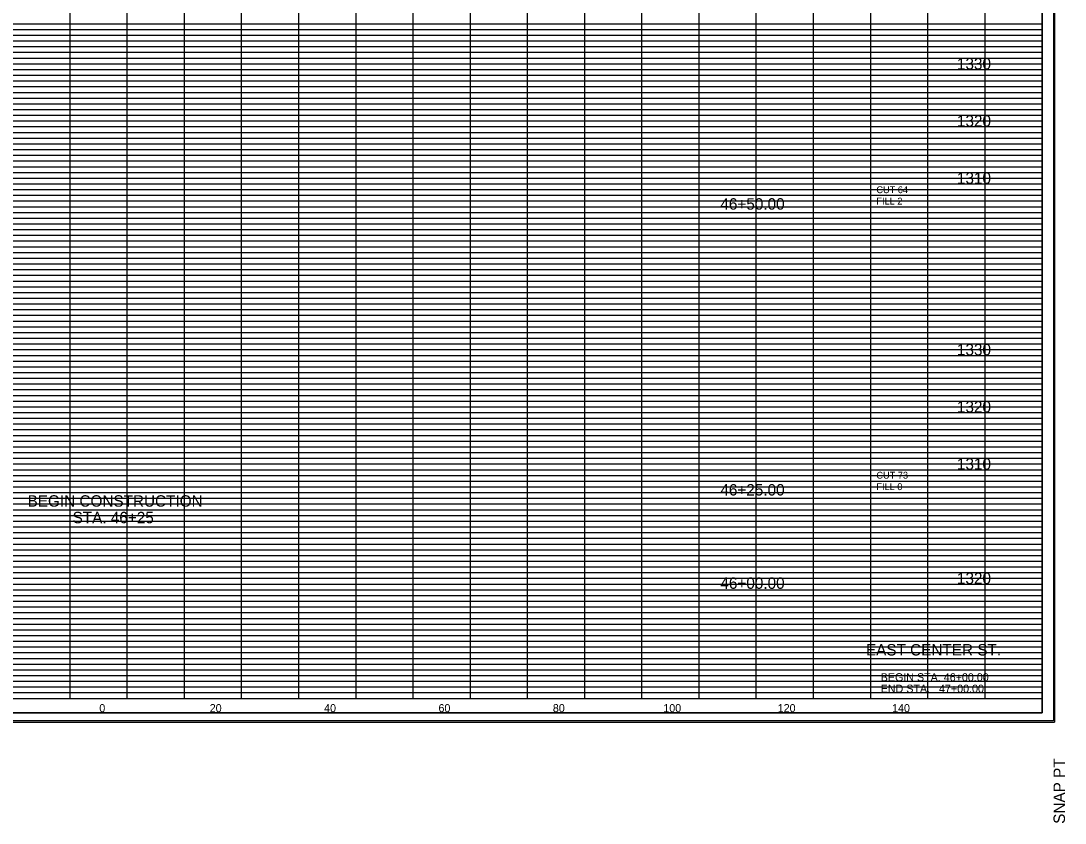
# Model space of a CAD drawing. Extents: x 980 to 1324, y 978 to 1767.
# Drawn here: x 1141.4 to 1324, y 978.2 to 1118.5 of the extents above; entities that cross this region are included whole.
import ezdxf

# ---------------------------------------------------------------- set-up
doc = ezdxf.new("R2010")
doc.units = 0
for name, color, linetype in [('DESIGN - SHEET - Corner Text', 7, 'Continuous'), ('DESIGN - SHEET - Light Grid', 7, 'Continuous'), ('DESIGN - SHEET - Linework', 7, 'Continuous'), ('DESIGN - SHEET - Plot Shape', 7, 'Continuous'), ('DESIGN - TYPICAL - Text', 7, 'Continuous')]:
    doc.layers.add(name, color=color, linetype=linetype)

# ---------------------------------------------------------------- blocks, each defined once
blk = doc.blocks.new('XSTSHT')
at = {"layer": 'DESIGN - SHEET - Light Grid'}
for p, q in [((8, 11.8), (16, 11.8)), ((8, 11.7), (16, 11.7)), ((16, 11.8), (24, 11.8)), ((16, 11.7), (24, 11.7)), ((24, 11.8), (32, 11.8)), ((24, 11.7), (32, 11.7)), ((8, 11.6), (16, 11.6)), ((16, 11.6), (24, 11.6)), ((24, 11.6), (32, 11.6)), ((8, 11.5), (16, 11.5)), ((8, 11.4), (16, 11.4)), ((16, 11.5), (24, 11.5)), ((16, 11.4), (24, 11.4)), ((24, 11.5), (32, 11.5)), ((24, 11.4), (32, 11.4)), ((8, 11.3), (16, 11.3)), ((8, 11.2), (16, 11.2)), ((16, 11.3), (24, 11.3)), ((16, 11.2), (24, 11.2)), ((24, 11.3), (32, 11.3)), ((24, 11.2), (32, 11.2)), ((8, 11.1), (16, 11.1)), ((16, 11.1), (24, 11.1)), ((24, 11.1), (32, 11.1)), ((8, 10.9), (16, 10.9)), ((8, 10.8), (16, 10.8)), ((16, 10.9), (24, 10.9)), ((16, 10.8), (24, 10.8)), ((24, 10.9), (32, 10.9)), ((24, 10.8), (32, 10.8)), ((8, 10.7), (16, 10.7)), ((8, 10.6), (16, 10.6)), ((16, 10.7), (24, 10.7)), ((16, 10.6), (24, 10.6)), ((24, 10.7), (32, 10.7)), ((24, 10.6), (32, 10.6)), ((8, 10.5), (16, 10.5)), ((16, 10.5), (24, 10.5)), ((24, 10.5), (32, 10.5)), ((8, 10.4), (16, 10.4)), ((8, 10.3), (16, 10.3)), ((16, 10.4), (24, 10.4)), ((16, 10.3), (24, 10.3)), ((24, 10.4), (32, 10.4)), ((24, 10.3), (32, 10.3)), ((8, 10.2), (16, 10.2)), ((8, 10.1), (16, 10.1)), ((16, 10.2), (24, 10.2)), ((16, 10.1), (24, 10.1)), ((24, 10.2), (32, 10.2)), ((24, 10.1), (32, 10.1)), ((8, 9.9), (16, 9.9)), ((16, 9.9), (24, 9.9)), ((24, 9.9), (32, 9.9)), ((8, 9.8), (16, 9.8)), ((8, 9.7), (16, 9.7)), ((16, 9.8), (24, 9.8)), ((16, 9.7), (24, 9.7)), ((24, 9.8), (32, 9.8)), ((24, 9.7), (32, 9.7)), ((8, 9.6), (16, 9.6)), ((8, 9.5), (16, 9.5)), ((16, 9.6), (24, 9.6)), ((16, 9.5), (24, 9.5)), ((24, 9.6), (32, 9.6)), ((24, 9.5), (32, 9.5)), ((8, 9.4), (16, 9.4)), ((16, 9.4), (24, 9.4)), ((24, 9.4), (32, 9.4)), ((8, 9.3), (16, 9.3)), ((8, 9.2), (16, 9.2)), ((16, 9.3), (24, 9.3)), ((16, 9.2), (24, 9.2)), ((24, 9.3), (32, 9.3)), ((24, 9.2), (32, 9.2)), ((8, 9.1), (16, 9.1)), ((16, 9.1), (24, 9.1)), ((24, 9.1), (32, 9.1)), ((8, 8.9), (16, 8.9)), ((8, 8.8), (16, 8.8)), ((16, 8.9), (24, 8.9)), ((16, 8.8), (24, 8.8)), ((24, 8.9), (32, 8.9)), ((24, 8.8), (32, 8.8)), ((8, 8.7), (16, 8.7)), ((8, 8.6), (16, 8.6)), ((16, 8.7), (24, 8.7)), ((16, 8.6), (24, 8.6)), ((24, 8.7), (32, 8.7)), ((24, 8.6), (32, 8.6)), ((8, 8.5), (16, 8.5)), ((8, 8.4), (16, 8.4)), ((16, 8.5), (24, 8.5)), ((16, 8.4), (24, 8.4)), ((24, 8.5), (32, 8.5)), ((24, 8.4), (32, 8.4)), ((8, 8.3), (16, 8.3)), ((16, 8.3), (24, 8.3)), ((24, 8.3), (32, 8.3)), ((8, 8.2), (16, 8.2)), ((8, 8.1), (16, 8.1)), ((16, 8.2), (24, 8.2)), ((16, 8.1), (24, 8.1)), ((24, 8.2), (32, 8.2)), ((24, 8.1), (32, 8.1)), ((8, 7.9), (16, 7.9)), ((16, 7.9), (24, 7.9)), ((24, 7.9), (32, 7.9)), ((8, 7.8), (16, 7.8)), ((8, 7.7), (16, 7.7)), ((16, 7.8), (24, 7.8)), ((16, 7.7), (24, 7.7)), ((24, 7.8), (32, 7.8)), ((24, 7.7), (32, 7.7)), ((8, 7.6), (16, 7.6)), ((8, 7.5), (16, 7.5)), ((16, 7.6), (24, 7.6)), ((16, 7.5), (24, 7.5)), ((24, 7.6), (32, 7.6)), ((24, 7.5), (32, 7.5)), ((8, 7.4), (16, 7.4)), ((16, 7.4), (24, 7.4)), ((24, 7.4), (32, 7.4)), ((8, 7.3), (16, 7.3)), ((8, 7.2), (16, 7.2)), ((16, 7.3), (24, 7.3)), ((16, 7.2), (24, 7.2)), ((24, 7.3), (32, 7.3)), ((24, 7.2), (32, 7.2)), ((8, 7.1), (16, 7.1)), ((16, 7.1), (24, 7.1)), ((24, 7.1), (32, 7.1)), ((8, 6.9), (16, 6.9)), ((8, 6.8), (16, 6.8)), ((16, 6.9), (24, 6.9)), ((16, 6.8), (24, 6.8)), ((24, 6.9), (32, 6.9)), ((24, 6.8), (32, 6.8)), ((8, 6.7), (16, 6.7)), ((8, 6.6), (16, 6.6)), ((16, 6.7), (24, 6.7)), ((16, 6.6), (24, 6.6)), ((24, 6.7), (32, 6.7)), ((24, 6.6), (32, 6.6)), ((8, 6.5), (16, 6.5)), ((8, 6.4), (16, 6.4)), ((16, 6.5), (24, 6.5)), ((16, 6.4), (24, 6.4)), ((24, 6.5), (32, 6.5)), ((24, 6.4), (32, 6.4)), ((8, 6.3), (16, 6.3)), ((16, 6.3), (24, 6.3)), ((24, 6.3), (32, 6.3)), ((8, 6.2), (16, 6.2)), ((8, 6.1), (16, 6.1)), ((16, 6.2), (24, 6.2)), ((16, 6.1), (24, 6.1)), ((24, 6.2), (32, 6.2)), ((24, 6.1), (32, 6.1)), ((8, 5.9), (16, 5.9)), ((16, 5.9), (24, 5.9)), ((24, 5.9), (32, 5.9)), ((8, 5.8), (16, 5.8)), ((8, 5.7), (16, 5.7)), ((16, 5.8), (24, 5.8)), ((16, 5.7), (24, 5.7)), ((24, 5.8), (32, 5.8)), ((24, 5.7), (32, 5.7)), ((8, 5.6), (16, 5.6)), ((8, 5.5), (16, 5.5)), ((16, 5.6), (24, 5.6)), ((16, 5.5), (24, 5.5)), ((24, 5.6), (32, 5.6)), ((24, 5.5), (32, 5.5)), ((8, 5.4), (16, 5.4)), ((8, 5.3), (16, 5.3)), ((16, 5.4), (24, 5.4)), ((16, 5.3), (24, 5.3)), ((24, 5.4), (32, 5.4)), ((24, 5.3), (32, 5.3)), ((8, 5.2), (16, 5.2)), ((16, 5.2), (24, 5.2)), ((24, 5.2), (32, 5.2)), ((8, 5.1), (16, 5.1)), ((16, 5.1), (24, 5.1)), ((24, 5.1), (32, 5.1)), ((8, 4.9), (16, 4.9)), ((8, 4.8), (16, 4.8)), ((16, 4.9), (24, 4.9)), ((16, 4.8), (24, 4.8)), ((24, 4.9), (32, 4.9)), ((24, 4.8), (32, 4.8)), ((8, 4.7), (16, 4.7)), ((8, 4.6), (16, 4.6)), ((16, 4.7), (24, 4.7)), ((16, 4.6), (24, 4.6)), ((24, 4.7), (32, 4.7)), ((24, 4.6), (32, 4.6)), ((8, 4.5), (16, 4.5)), ((8, 4.4), (16, 4.4)), ((16, 4.5), (24, 4.5)), ((16, 4.4), (24, 4.4)), ((24, 4.5), (32, 4.5)), ((24, 4.4), (32, 4.4)), ((8, 4.3), (16, 4.3)), ((8, 4.2), (16, 4.2)), ((16, 4.3), (24, 4.3)), ((16, 4.2), (24, 4.2)), ((24, 4.3), (32, 4.3)), ((24, 4.2), (32, 4.2)), ((8, 4.1), (16, 4.1)), ((16, 4.1), (24, 4.1)), ((24, 4.1), (32, 4.1)), ((8, 3.9), (16, 3.9)), ((16, 3.9), (24, 3.9)), ((24, 3.9), (32, 3.9)), ((8, 3.8), (16, 3.8)), ((8, 3.7), (16, 3.7)), ((16, 3.8), (24, 3.8)), ((16, 3.7), (24, 3.7)), ((24, 3.8), (32, 3.8)), ((24, 3.7), (32, 3.7)), ((8, 3.6), (16, 3.6)), ((8, 3.5), (16, 3.5)), ((16, 3.6), (24, 3.6)), ((16, 3.5), (24, 3.5)), ((24, 3.6), (32, 3.6)), ((24, 3.5), (32, 3.5)), ((8, 3.4), (16, 3.4)), ((8, 3.3), (16, 3.3)), ((16, 3.4), (24, 3.4)), ((16, 3.3), (24, 3.3)), ((24, 3.4), (32, 3.4)), ((24, 3.3), (32, 3.3)), ((8, 3.2), (16, 3.2)), ((16, 3.2), (24, 3.2)), ((24, 3.2), (32, 3.2)), ((8, 3.1), (16, 3.1)), ((16, 3.1), (24, 3.1)), ((24, 3.1), (32, 3.1)), ((8, 2.9), (16, 2.9)), ((8, 2.8), (16, 2.8)), ((16, 2.9), (24, 2.9)), ((16, 2.8), (24, 2.8)), ((24, 2.9), (32, 2.9)), ((24, 2.8), (32, 2.8)), ((8, 2.7), (16, 2.7)), ((8, 2.6), (16, 2.6)), ((16, 2.7), (24, 2.7)), ((16, 2.6), (24, 2.6)), ((24, 2.7), (32, 2.7)), ((24, 2.6), (32, 2.6)), ((8, 2.5), (16, 2.5)), ((8, 2.4), (16, 2.4)), ((16, 2.5), (24, 2.5)), ((16, 2.4), (24, 2.4)), ((24, 2.5), (32, 2.5)), ((24, 2.4), (32, 2.4)), ((8, 2.3), (16, 2.3)), ((8, 2.2), (16, 2.2)), ((16, 2.3), (24, 2.3)), ((16, 2.2), (24, 2.2)), ((24, 2.3), (32, 2.3)), ((24, 2.2), (32, 2.2)), ((8, 2.1), (16, 2.1)), ((16, 2.1), (24, 2.1)), ((24, 2.1), (32, 2.1)), ((8, 1.9), (16, 1.9)), ((16, 1.9), (24, 1.9)), ((24, 1.9), (32, 1.9)), ((8, 1.8), (16, 1.8)), ((8, 1.7), (16, 1.7)), ((16, 1.8), (24, 1.8)), ((16, 1.7), (24, 1.7)), ((24, 1.8), (32, 1.8)), ((24, 1.7), (32, 1.7)), ((8, 1.6), (16, 1.6)), ((8, 1.5), (16, 1.5)), ((16, 1.6), (24, 1.6)), ((16, 1.5), (24, 1.5)), ((24, 1.6), (32, 1.6)), ((24, 1.5), (32, 1.5)), ((8, 1.4), (16, 1.4)), ((8, 1.3), (16, 1.3)), ((16, 1.4), (24, 1.4)), ((16, 1.3), (24, 1.3)), ((24, 1.4), (32, 1.4)), ((24, 1.3), (32, 1.3)), ((8, 1.2), (16, 1.2)), ((8, 1.1), (16, 1.1)), ((16, 1.2), (24, 1.2)), ((16, 1.1), (24, 1.1)), ((24, 1.2), (32, 1.2)), ((24, 1.1), (32, 1.1)), ((8, 0.9), (16, 0.9)), ((8, 0.8), (16, 0.8)), ((16, 0.9), (24, 0.9)), ((16, 0.8), (24, 0.8)), ((24, 0.9), (32, 0.9)), ((24, 0.8), (32, 0.8)), ((8, 0.7), (16, 0.7)), ((8, 0.6), (16, 0.6)), ((16, 0.7), (24, 0.7)), ((16, 0.6), (24, 0.6)), ((24, 0.7), (32, 0.7)), ((24, 0.6), (32, 0.6)), ((8, 0.5), (16, 0.5)), ((8, 0.4), (16, 0.4)), ((16, 0.5), (24, 0.5)), ((16, 0.4), (24, 0.4)), ((24, 0.5), (32, 0.5)), ((24, 0.4), (32, 0.4)), ((8, 0.3), (16, 0.3)), ((8, 0.2), (16, 0.2)), ((16, 0.3), (24, 0.3)), ((16, 0.2), (24, 0.2)), ((24, 0.3), (32, 0.3)), ((24, 0.2), (32, 0.2)), ((8, 0.1), (16, 0.1)), ((16, 0.1), (24, 0.1)), ((24, 0.1), (32, 0.1))]:
    blk.add_line(p, q, dxfattribs=at)
at = {"layer": 'DESIGN - SHEET - Linework'}
for p, q in [((32.217, 21.414), (32.217, -0.414)), ((15, 0), (15, 21)), ((16, 0), (16, 21)), ((17, 0), (17, 21)), ((18, 0), (18, 21)), ((19, 0), (19, 21)), ((20, 0), (20, 21)), ((21, 0), (21, 21)), ((22, 0), (22, 21)), ((23, 0), (23, 21)), ((24, 0), (24, 21)), ((25, 0), (25, 21)), ((26, 0), (26, 21)), ((27, 0), (27, 21)), ((28, 0), (28, 20)), ((29, 0), (29, 20)), ((30, 0), (30, 20)), ((31, 0), (31, 20)), ((0, 11), (32, 11)), ((0, 10), (32, 10)), ((0, 9), (32, 9)), ((0, 8), (32, 8)), ((0, 7), (32, 7)), ((0, 6), (32, 6)), ((0, 5), (32, 5)), ((0, 4), (32, 4)), ((0, 3), (32, 3)), ((0, 2), (32, 2)), ((0, 1), (32, 1)), ((-1.823, -0.414), (32.217, -0.414))]:
    blk.add_line(p, q, dxfattribs=at)
blk.add_lwpolyline([(0, 21), (0, 0), (32, 0), (32, 21), (0, 21)], dxfattribs=at)
at = {"layer": 'DESIGN - SHEET - Plot Shape'}
for points in [[(-1.803, 21.394), (32.197, 21.394), (32.197, -0.394), (-1.803, -0.394)], [(-0.85, 21), (32, 21), (32, -0.25), (-0.85, -0.25)]]:
    blk.add_lwpolyline(points, close=True, dxfattribs=at)
at = {"layer": 'DESIGN - SHEET - Corner Text'}
blk.add_text('SNAP PT  ', height=0.2, rotation=90, dxfattribs=at).set_placement((32.397, -2.194))

msp = doc.modelspace()

# ---------------------------------------------------------------- linework, layer by layer
at = {"layer": 'DESIGN - SHEET - Plot Shape'}
msp.add_lwpolyline([(991.5, 997.5), (1320, 997.5), (1320, 1210), (991.5, 1210)], close=True, dxfattribs=at)

# ---------------------------------------------------------------- block references
at = {"layer": 'DESIGN - SHEET - Plot Shape', "xscale": 10, "yscale": 10}
msp.add_blockref('XSTSHT', (1000, 1000), dxfattribs=at)

# ---------------------------------------------------------------- texts
at = {"layer": 'DESIGN - SHEET - Corner Text'}
for s, height, p in [('EAST CENTER ST.', 2, (1289.17, 1007.5)), ('BEGIN STA. 46+00.00', 1.4, (1291.75, 1003)), ('END STA.   47+00.00', 1.4, (1291.75, 1001))]:
    msp.add_text(s, height=height, dxfattribs=at).set_placement(p)
at = {"layer": 'DESIGN - TYPICAL - Text'}
for s, height, p in [('     1330     ', 2, (1301.37, 1110)), ('     1320     ', 2, (1301.37, 1100)), ('     1310     ', 2, (1301.37, 1090)), ('CUT 64', 1.2, (1291, 1088.37)), ('     46+50.00     ', 2, (1260, 1085.48)), ('FILL 2', 1.2, (1291, 1086.37)), ('     1330     ', 2, (1301.37, 1060)), ('     1320     ', 2, (1301.37, 1050)), ('     1310     ', 2, (1301.37, 1040)), ('CUT 73', 1.2, (1291, 1038.43)), ('     46+25.00     ', 2, (1260, 1035.48)), ('FILL 0', 1.2, (1291, 1036.43)), ('BEGIN CONSTRUCTION', 2, (1142.57, 1033.53)), ('STA. 46+25', 2, (1150.44, 1030.63)), ('     46+00.00     ', 2, (1260, 1019.16)), ('     1320     ', 2, (1301.37, 1020)), ('     0     ', 1.4, (1152.51, 997.6)), ('     0     ', 1.4, (1152.51, 997.6)), ('     20     ', 1.4, (1171.82, 997.6)), ('     40     ', 1.4, (1191.82, 997.6)), ('     60     ', 1.4, (1211.82, 997.6)), ('     80     ', 1.4, (1231.82, 997.6)), ('     100     ', 1.4, (1251.14, 997.6)), ('     120     ', 1.4, (1271.14, 997.6)), ('     140     ', 1.4, (1291.14, 997.6))]:
    msp.add_text(s, height=height, dxfattribs=at).set_placement(p)

doc.saveas('drawing.dxf')
